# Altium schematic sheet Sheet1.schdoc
size 310 x 205 mm
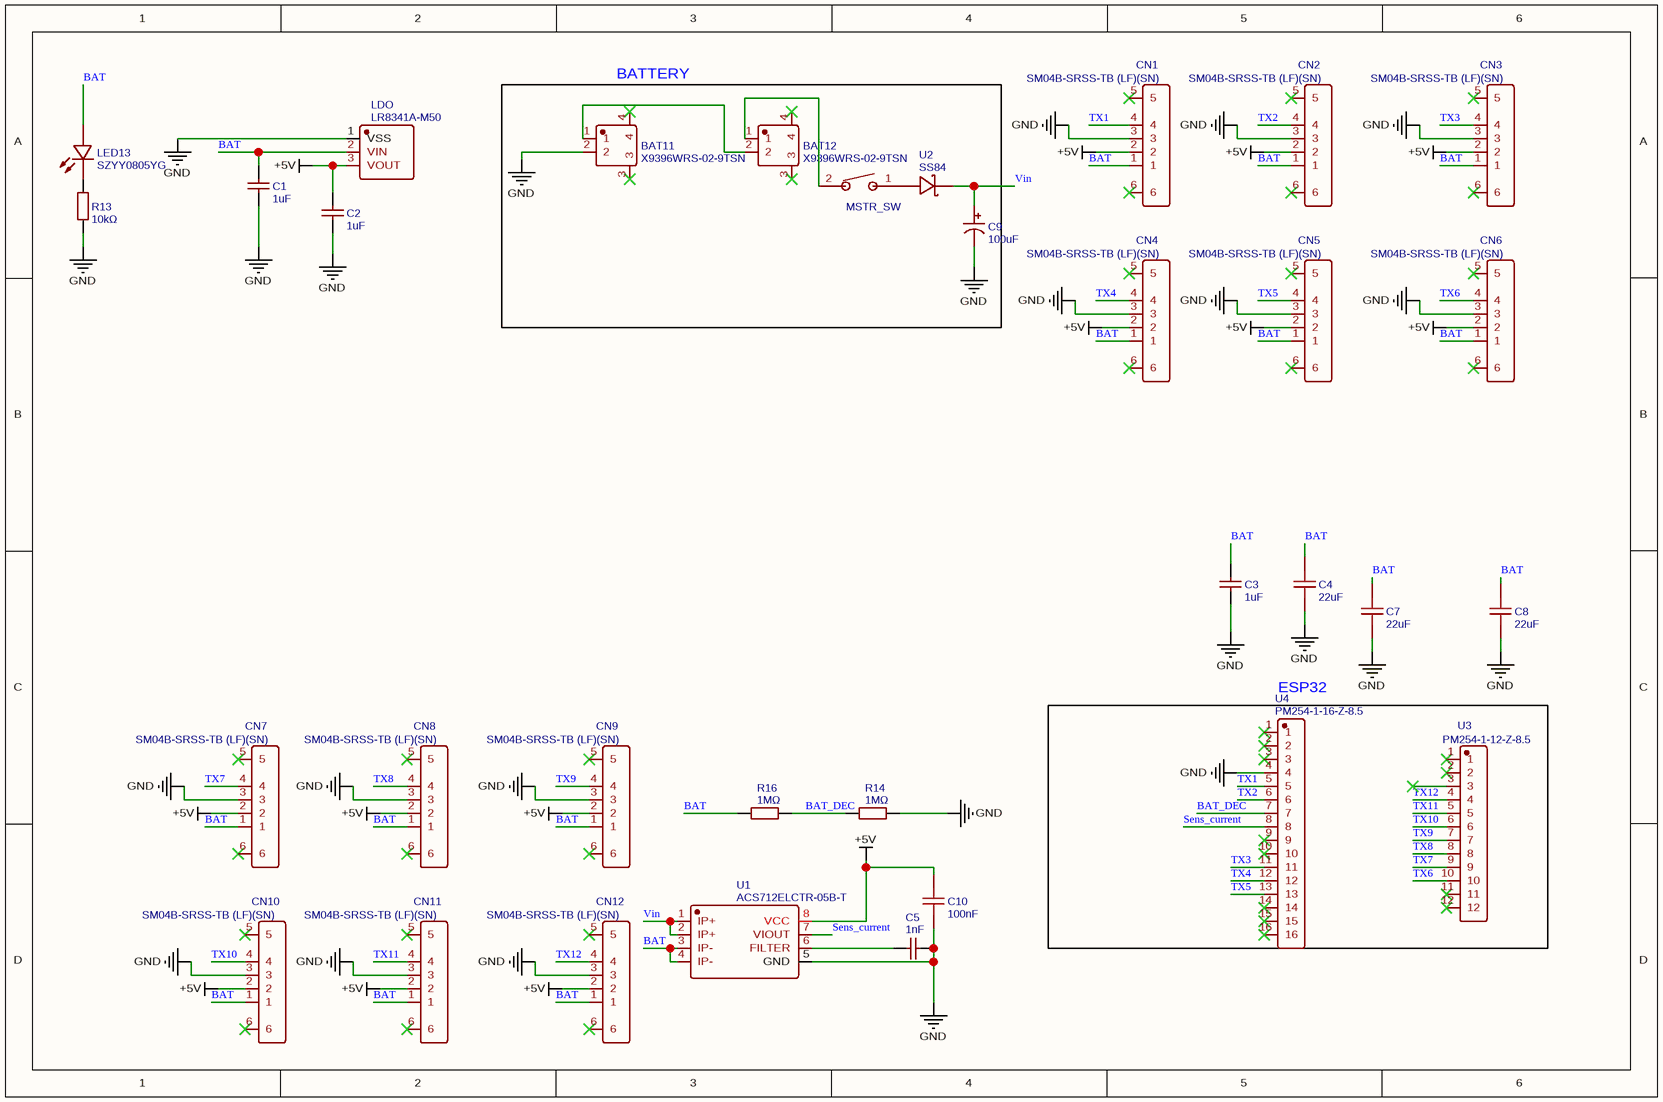
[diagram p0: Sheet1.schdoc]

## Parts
BAT11  X9396WRS-02-9TSN  [CONN-SMD_X9396WRS-02-9TSN]
BAT12  X9396WRS-02-9TSN  [CONN-SMD_X9396WRS-02-9TSN]
C1  1uF  [C0805]
C2  1uF  [C0805]
C3  1uF  [C0805]
C4  22uF  [C0805]
C5  1nF  [C0402]
C7  22uF  [C0805]
C8  22uF  [C0805]
C9  100uF  [CAP-SMD_BD5.0-L5.3-W5.3-RD]
C10  100nF  [C0402]
CN1  SM04B-SRSS-TB (LF)(SN)  [CONN-SMD_4P-P1.00_SM04B-SRSS-TB-LF-SN]
CN2  SM04B-SRSS-TB (LF)(SN)  [CONN-SMD_4P-P1.00_SM04B-SRSS-TB-LF-SN]
CN3  SM04B-SRSS-TB (LF)(SN)  [CONN-SMD_4P-P1.00_SM04B-SRSS-TB-LF-SN]
CN4  SM04B-SRSS-TB (LF)(SN)  [CONN-SMD_4P-P1.00_SM04B-SRSS-TB-LF-SN]
CN5  SM04B-SRSS-TB (LF)(SN)  [CONN-SMD_4P-P1.00_SM04B-SRSS-TB-LF-SN]
CN6  SM04B-SRSS-TB (LF)(SN)  [CONN-SMD_4P-P1.00_SM04B-SRSS-TB-LF-SN]
CN7  SM04B-SRSS-TB (LF)(SN)  [CONN-SMD_4P-P1.00_SM04B-SRSS-TB-LF-SN]
CN8  SM04B-SRSS-TB (LF)(SN)  [CONN-SMD_4P-P1.00_SM04B-SRSS-TB-LF-SN]
CN9  SM04B-SRSS-TB (LF)(SN)  [CONN-SMD_4P-P1.00_SM04B-SRSS-TB-LF-SN]
CN10  SM04B-SRSS-TB (LF)(SN)  [CONN-SMD_4P-P1.00_SM04B-SRSS-TB-LF-SN]
CN11  SM04B-SRSS-TB (LF)(SN)  [CONN-SMD_4P-P1.00_SM04B-SRSS-TB-LF-SN]
CN12  SM04B-SRSS-TB (LF)(SN)  [CONN-SMD_4P-P1.00_SM04B-SRSS-TB-LF-SN]
LDO  LR8341A-M50  [SOT-89-3_L4.5-W2.5-P1.50-LS4.2-BR]
LED13  SZYY0805YG  [LED0805-R-RD_GREEN]
MSTR_SW  RS601HL-1010011BB  [SW-TH_RS601HL-1010011BB]  (value not drawn)
R13  10kΩ  [R0805]
R14  1MΩ  [R0805]
R16  1MΩ  [R0805]
U1  ACS712ELCTR-05B-T  [SOIC-8_L5.0-W4.0-P1.27-LS6.0-BL]
U2  SS84  [SMC_L6.9-W5.9-LS7.9-RD]
U3  PM254-1-12-Z-8.5  [HDR-TH_12P-P2.54-V-F]
U4  PM254-1-16-Z-8.5  [HDR-TH_16P-P2.54-V-F-A]

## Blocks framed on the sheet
BATTERY: BAT11 BAT12 C9 MSTR_SW U2
ESP32: U3 U4

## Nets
+5V: C2.2 C10.2 CN1.2 CN2.2 CN3.2 CN4.2 CN5.2 CN6.2 CN7.2 CN8.2 CN9.2 CN10.2 CN11.2 CN12.2 LDO.3(VOUT) U1.8(VCC)
GND: BAT11.2 C1.1 C2.1 C3.1 C4.1 C5.2 C7.1 C8.1 C9.2 C10.1 CN1.3 CN2.3 CN3.3 CN4.3 CN5.3 CN6.3 CN7.3 CN8.3 CN9.3 CN10.3 CN11.3 CN12.3 LDO.1(VSS) R13.1 R14.2 U1.5(GND) U4.4
BAT: C1.2 C3.2 C4.2 C7.2 C8.2 CN1.1 CN2.1 CN3.1 CN4.1 CN5.1 CN6.1 CN7.1 CN8.1 CN9.1 CN10.1 CN11.1 CN12.1 LDO.2(VIN) LED13.1(+) R16.1 U1.3(IP-) U1.4(IP-)
BAT_DEC: R14.1 R16.2 U4.7
Sens_current: U1.7(VIOUT) U4.8
TX1: CN1.4 U4.5
TX2: CN2.4 U4.6
TX3: CN3.4 U4.11
TX4: CN4.4 U4.12
TX5: CN5.4 U4.13
TX6: CN6.4 U3.10
TX7: CN7.4 U3.9
TX8: CN8.4 U3.8
TX9: CN9.4 U3.7
TX10: CN10.4 U3.6
TX11: CN11.4 U3.5
TX12: CN12.4 U3.4
Vin: C9.1 U1.1(IP+) U1.2(IP+) U2.1(K)
NetBAT11_1: BAT11.1 BAT12.2
NetBAT12_1: BAT12.1 MSTR_SW.2
NetC5_1: C5.1 U1.6(FILTER)
NetLED13_2: LED13.2(-) R13.2
NetMSTR_SW_1: MSTR_SW.1 U2.2(A)

Not connected (* = marked no-connect by the designer): BAT11 3* 4*; BAT12 3* 4*; CN1 5* 6*; CN2 5* 6*; CN3 5* 6*; CN4 5* 6*; CN5 5* 6*; CN6 5* 6*; CN7 5* 6*; CN8 5* 6*; CN9 5* 6*; CN10 5* 6*; CN11 5* 6*; CN12 5* 6*; U3 1* 2* 3* 11* 12*; U4 1* 2* 3* 9* 10* 14* 15* 16*

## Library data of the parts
BAT11 BAT12 = X9396WRS-02-9TSN: Manufacturer: XKB Connectivity(中国星坤); Contributor: LCSC
C1-C3 = 1uF: Manufacturer Part: CL21B105KBFNNNE; Manufacturer: SAMSUNG(三星); nameAlias: Capacitance
C4 C7 C8 = 22uF: Manufacturer: SAMSUNG(三星); Manufacturer Part: CL21A226MAYNNNE; nameAlias: Capacitance; Contributor: LCSC
C5 = 1nF: Manufacturer: FH(风华); Manufacturer Part: 0402B102K500NT; nameAlias: Capacitance
C9 = 100uF: Manufacturer: ST(先科); Manufacturer Part: CS1A101M-CRD54; nameAlias: Capacitance
C10 = 100nF: Manufacturer: SAMSUNG(三星); Manufacturer Part: CL05B104KB54PNC; nameAlias: Capacitance; Contributor: LCSC
CN1-CN12 = SM04B-SRSS-TB (LF)(SN): Manufacturer: JST; Contributor: LCSC
LDO = LR8341A-M50: Manufacturer: LR(朗瑞); Contributor: LCSC
LED13 = SZYY0805YG: Manufacturer: yongyu(永裕光电); Contributor: LCSC
MSTR_SW = RS601HL-1010011BB: Manufacturer: HCTL(华灿天禄); Contributor: lcsc
R13 = 10kΩ: Manufacturer: UNI-ROYAL(厚声); Manufacturer Part: 0805W8F1002T5E; nameAlias: Resistance; Resistance (Ohms): 10K
R14 R16 = 1MΩ: Manufacturer: UNI-ROYAL(厚声); Manufacturer Part: 0805W8F1004T5E; nameAlias: Resistance; Resistance (Ohms): 1M
U1 = ACS712ELCTR-05B-T: Manufacturer: ALLEGRO(美国埃戈罗)
U2 = SS84: Manufacturer: GOODWORK(固得沃克); Contributor: lcsc
U3 = PM254-1-12-Z-8.5: Manufacturer: HCTL(华灿天禄); Contributor: LCSC
U4 = PM254-1-16-Z-8.5: Manufacturer: HCTL(华灿天禄); Contributor: LCSC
